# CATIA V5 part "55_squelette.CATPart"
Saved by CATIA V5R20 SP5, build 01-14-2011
Part number: 55_squelette
Publications: "Plan.1", "Point.1", "Point.3", "Point.4", "Point.5", "Plan yz", "Plan zx", "Plan.3", "Plan.4"
Bounding box of the stored display mesh (mm): x 0 to 0, y 140.362 to 156.362, z 132 to 140.25
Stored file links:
  C:\Documents and Settings\anizard\Bureau\13\55_squelette.CATPart
  C:\Documents and Settings\anizard\Bureau\13\anizard.CATProduct
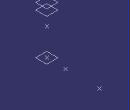
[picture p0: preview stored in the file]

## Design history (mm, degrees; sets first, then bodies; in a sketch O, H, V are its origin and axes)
Set1
  Plane1: linked copy from another document
  Point1: linked copy from another document
  Line1: linked copy from another document
Body1 (main body)
  Plane2: type Offset, RefPlane Plane1, Offset 3
  Point2: type OnPlane, Support Plane2, RefPoint Point1, H 0, V 0, Direction (1, 0, 0)
  Point3: (0, 16, 0), relative to Point2
  Point4: (0, 5.75, 0), relative to Point2
  Point5: type OnCurve, Support Line1, RefPoint Point2, Length 8.25
  Plane3: type Offset, RefPlane Plane2, Offset 12.5
  Plane4: type Offset, RefPlane Plane3, Offset 2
